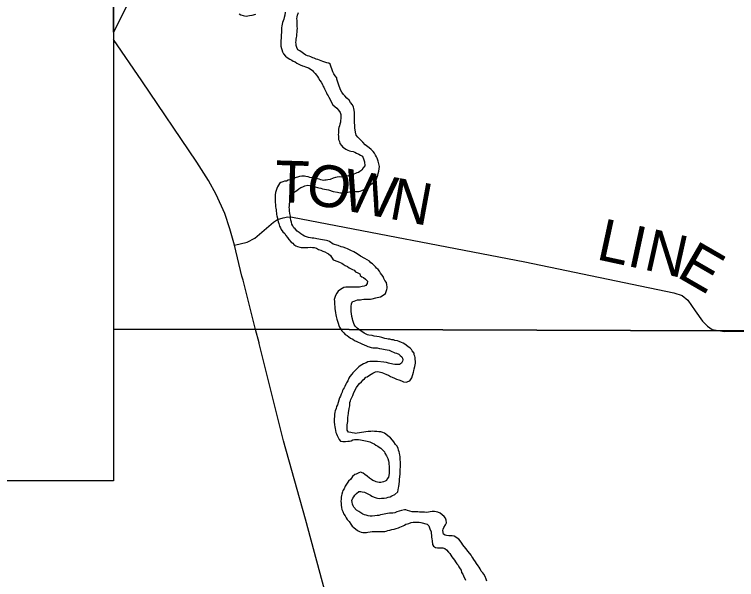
# Model space of a CAD drawing. Extents: x 0 to 34, y 0 to 22.
# Drawn here: x 5.775 to 6.756, y 14.874 to 15.642 of the extents above; entities that cross this region are included whole.
import ezdxf

# ---------------------------------------------------------------- set-up
doc = ezdxf.new("R2010")
doc.units = 0
for name, color, linetype in [('Default', 7, 'Continuous'), ('GM_X_Corporation', 7, 'Continuous'), ('GM_X_Minor_River', 7, 'Continuous'), ('GM_X_Township_Road', 7, 'Continuous'), ('GM_X_Township_Road_Text', 7, 'Continuous'), ('SH_Text', 7, 'Continuous')]:
    doc.layers.add(name, color=color, linetype=linetype)

msp = doc.modelspace()

# ---------------------------------------------------------------- linework, layer by layer
at = {"layer": 'Default'}
msp.add_lwpolyline([(5.90994, 15.72564), (6.64074, 17.07843), (5.90994, 15.61811)], close=True, dxfattribs=at)
at = {"layer": 'GM_X_Corporation'}
msp.add_lwpolyline([(5.90994, 15.72564), (5.90994, 15.21376), (6.10258, 15.21454), (6.73943, 15.21199), (6.94963, 15.21339), (8.01532, 15.22729), (7.992, 16.45338)], dxfattribs=at)
msp.add_lwpolyline([(3.69009, 15.2048), (3.5209, 15.20411), (2.73663, 15.2014), (2.74225, 14.8151), (2.77525, 14.15375), (2.77611, 14.09996), (8.03831, 14.09996), (8.03504, 14.24979), (8.03488, 14.25722), (8.02966, 14.49633), (8.02618, 14.65547), (8.01532, 15.22729), (6.94963, 15.21339), (6.73943, 15.21199), (6.10258, 15.21454), (5.90994, 15.21376), (5.90994, 15.00852), (3.69009, 15.00852)], close=True, dxfattribs=at)
at = {"layer": 'GM_X_Minor_River'}
for points in [[(6.08029, 15.64305), (6.08293, 15.6415), (6.08596, 15.6407), (6.08786, 15.6403), (6.08975, 15.6399), (6.09204, 15.64025), (6.09471, 15.6406), (6.09814, 15.64132), (6.10309, 15.6424)], [(6.14304, 15.64535), (6.14261, 15.64117), (6.14143, 15.63814), (6.14103, 15.63587), (6.14024, 15.6336), (6.13945, 15.63094), (6.13866, 15.62868), (6.13825, 15.62678), (6.13784, 15.62374), (6.13782, 15.62184), (6.13779, 15.61956), (6.13776, 15.61728), (6.13773, 15.61462), (6.13771, 15.61272), (6.13729, 15.61006), (6.13687, 15.60665), (6.13685, 15.60475), (6.13718, 15.60094), (6.13716, 15.59904), (6.13935, 15.59141), (6.14083, 15.58836), (6.14346, 15.58528), (6.14572, 15.58374), (6.14949, 15.58141), (6.15214, 15.57986), (6.15402, 15.5787), (6.15667, 15.57752), (6.15893, 15.57598), (6.16157, 15.57442), (6.16347, 15.57364), (6.16649, 15.57247), (6.16838, 15.57168), (6.17065, 15.5709), (6.17444, 15.56933), (6.1767, 15.56816), (6.1801, 15.56584)], [(6.20784, 15.5643), (6.20415, 15.57468), (6.20226, 15.57584), (6.19961, 15.57626), (6.19696, 15.57705), (6.19431, 15.57822), (6.19204, 15.57901), (6.18712, 15.58097), (6.18522, 15.58137), (6.1822, 15.58254), (6.18031, 15.58333), (6.17804, 15.58449), (6.17577, 15.58528), (6.17312, 15.58607), (6.17085, 15.58686), (6.16783, 15.58918), (6.16595, 15.59034), (6.16293, 15.59266), (6.16029, 15.59421), (6.15881, 15.59727), (6.15808, 15.59993), (6.15772, 15.60184), (6.15737, 15.60451), (6.15778, 15.6064), (6.1578, 15.6083), (6.15821, 15.61058), (6.15861, 15.61247), (6.15864, 15.61475), (6.15906, 15.61855), (6.15908, 15.62045), (6.1595, 15.62348), (6.15915, 15.62539), (6.15919, 15.62919), (6.15922, 15.63147), (6.15925, 15.63413), (6.15889, 15.63604), (6.15931, 15.63869), (6.15971, 15.64097), (6.1609, 15.64476)], [(6.1801, 15.56584), (6.18122, 15.56393), (6.18385, 15.56162), (6.18535, 15.5597), (6.18684, 15.55778), (6.18833, 15.55548), (6.1902, 15.55242), (6.19207, 15.55012), (6.19356, 15.54706), (6.19429, 15.54515), (6.19541, 15.54323), (6.19652, 15.54094), (6.19726, 15.53903), (6.19912, 15.53559), (6.20023, 15.53329), (6.20135, 15.53138), (6.20209, 15.52947), (6.2079, 15.51932)], [(6.20807, 15.40158), (6.21402, 15.40069), (6.21593, 15.4003), (6.21821, 15.3999), (6.22012, 15.39989), (6.22279, 15.40025), (6.22545, 15.40062), (6.22812, 15.4006), (6.23041, 15.40096), (6.23231, 15.40133), (6.23422, 15.40132), (6.23689, 15.40168), (6.24031, 15.40166), (6.24298, 15.40164), (6.24489, 15.40201), (6.24718, 15.40275), (6.25138, 15.40462), (6.2552, 15.40688), (6.26018, 15.41179), (6.26553, 15.41518), (6.26862, 15.42391), (6.26939, 15.42618), (6.27017, 15.42922), (6.27057, 15.43226), (6.27097, 15.4353), (6.2706, 15.4372), (6.27022, 15.43911), (6.26985, 15.44101), (6.2691, 15.44292), (6.26798, 15.44673), (6.26723, 15.44864), (6.26572, 15.45093), (6.2642, 15.4536), (6.26231, 15.4559), (6.25966, 15.45858), (6.257, 15.46088), (6.25511, 15.46203), (6.2517, 15.4651), (6.24867, 15.46854), (6.24601, 15.47084), (6.24374, 15.47314), (6.24184, 15.47543), (6.23919, 15.47811), (6.23845, 15.48192), (6.23772, 15.48801), (6.23701, 15.49829), (6.23702, 15.50019), (6.23703, 15.50209), (6.23704, 15.50399), (6.23705, 15.50627), (6.23707, 15.50894), (6.2367, 15.51198), (6.23633, 15.51427), (6.23596, 15.51617), (6.23445, 15.51922), (6.2318, 15.52228), (6.22992, 15.52572), (6.22689, 15.5284), (6.22385, 15.53147), (6.22234, 15.53338), (6.22007, 15.53643), (6.21818, 15.53949), (6.21705, 15.54254), (6.2163, 15.54483), (6.21518, 15.5475), (6.21443, 15.55017), (6.2133, 15.55398), (6.21293, 15.55588), (6.21104, 15.55855), (6.20915, 15.56161), (6.20784, 15.5643)], [(6.2079, 15.51932), (6.2131, 15.5148), (6.21537, 15.51212), (6.21764, 15.50869), (6.21839, 15.50602), (6.21875, 15.50297), (6.21874, 15.50107), (6.21834, 15.49765), (6.21795, 15.49575), (6.21718, 15.49309), (6.21678, 15.49082), (6.21601, 15.48854), (6.21562, 15.48626), (6.21522, 15.4836), (6.21521, 15.48094), (6.21482, 15.47904), (6.21519, 15.47675), (6.21518, 15.47485), (6.21554, 15.47219), (6.21667, 15.46952), (6.21742, 15.46685), (6.21931, 15.46418), (6.2212, 15.46188), (6.22348, 15.46034), (6.22538, 15.45881), (6.22804, 15.45765), (6.23032, 15.45687), (6.23222, 15.45648), (6.23527, 15.45608), (6.23755, 15.45492), (6.23982, 15.45339), (6.24286, 15.45223), (6.24514, 15.45107), (6.2478, 15.44953), (6.24968, 15.44457), (6.25081, 15.4419), (6.25116, 15.43619), (6.24886, 15.43355), (6.24732, 15.43052), (6.24427, 15.42863), (6.24235, 15.42751), (6.24045, 15.42676), (6.23854, 15.42601), (6.23625, 15.42527), (6.23396, 15.42414), (6.23129, 15.4234), (6.229, 15.42265), (6.22709, 15.42228), (6.22366, 15.42155), (6.22137, 15.42156), (6.21908, 15.4212), (6.21718, 15.42121), (6.21375, 15.42085), (6.21146, 15.42049), (6.20804, 15.41963)], [(6.20804, 15.41963), (6.20416, 15.41769), (6.20074, 15.41735), (6.19883, 15.41699), (6.19693, 15.41702), (6.19503, 15.41666), (6.19124, 15.41746), (6.18935, 15.41825), (6.18669, 15.41866), (6.18441, 15.41907), (6.18138, 15.41986), (6.17948, 15.41988), (6.17645, 15.42068), (6.17418, 15.42147), (6.17114, 15.42188), (6.16925, 15.42229), (6.16545, 15.42233), (6.1624, 15.42199), (6.15972, 15.42088), (6.15782, 15.42052), (6.15515, 15.41941), (6.15248, 15.41869), (6.1498, 15.41758), (6.14713, 15.41685), (6.14484, 15.41573), (6.14217, 15.41538), (6.13988, 15.41465), (6.13721, 15.41354), (6.1353, 15.41243), (6.13258, 15.4079), (6.13179, 15.40563), (6.12983, 15.40033), (6.12941, 15.39691), (6.12937, 15.39387), (6.12934, 15.39159), (6.12931, 15.38855), (6.12928, 15.38627), (6.12964, 15.38436), (6.12999, 15.38246), (6.12997, 15.38056), (6.13033, 15.37866), (6.13068, 15.37675), (6.13066, 15.37447), (6.13101, 15.37256), (6.13137, 15.37028), (6.13172, 15.36837), (6.13245, 15.36532), (6.1328, 15.36266), (6.13353, 15.36037), (6.13426, 15.35808), (6.135, 15.35617), (6.13536, 15.35427), (6.13647, 15.35197), (6.13759, 15.35006), (6.13982, 15.34661), (6.14246, 15.3443), (6.14395, 15.34162), (6.1462, 15.33893), (6.14806, 15.33625), (6.15106, 15.33279), (6.15332, 15.33125), (6.15482, 15.32933), (6.15746, 15.32778), (6.15973, 15.32661), (6.16276, 15.32581), (6.16466, 15.32541), (6.17112, 15.32534), (6.17378, 15.3253), (6.17721, 15.32602), (6.17987, 15.32561), (6.18252, 15.3252), (6.18555, 15.3244), (6.1882, 15.32285), (6.19122, 15.32168), (6.19425, 15.3205), (6.1969, 15.31933), (6.19992, 15.31777), (6.2018, 15.31661), (6.20444, 15.31468), (6.20819, 15.30886)], [(6.20816, 15.33001), (6.20315, 15.3337), (6.20088, 15.33448), (6.19898, 15.33489), (6.19367, 15.33571), (6.19102, 15.33612), (6.18875, 15.33691), (6.18609, 15.33732), (6.18419, 15.33772), (6.18192, 15.33813), (6.17964, 15.33816), (6.17736, 15.33856), (6.17471, 15.33898), (6.17205, 15.33977), (6.16941, 15.34094), (6.16676, 15.34211), (6.16412, 15.34404), (6.16186, 15.34597), (6.15922, 15.34752), (6.1566, 15.35059), (6.15472, 15.35214), (6.15323, 15.35482), (6.15212, 15.35711), (6.15139, 15.35978), (6.15066, 15.36245), (6.15031, 15.36511), (6.14997, 15.36816), (6.14925, 15.37159), (6.14891, 15.37501), (6.14895, 15.37805), (6.14859, 15.37996), (6.149, 15.38223), (6.14903, 15.38527), (6.14983, 15.38831), (6.15063, 15.39134), (6.1518, 15.39437), (6.15336, 15.39739), (6.15453, 15.39965), (6.15645, 15.40153), (6.15875, 15.40265), (6.16144, 15.40527), (6.16412, 15.40676), (6.16679, 15.40787), (6.16947, 15.40898), (6.17366, 15.41007), (6.17859, 15.40925), (6.18087, 15.40884), (6.18389, 15.40767), (6.18693, 15.40687), (6.18882, 15.40647), (6.19148, 15.40606), (6.19375, 15.40527), (6.1964, 15.40448), (6.19906, 15.40407), (6.20171, 15.40366), (6.20807, 15.40158)], [(6.30982, 15.14332), (6.31211, 15.14444), (6.31517, 15.14823), (6.3175, 15.15582), (6.31789, 15.15772), (6.31828, 15.16038), (6.31906, 15.1638), (6.31985, 15.16835), (6.31951, 15.17596), (6.31914, 15.17787), (6.31839, 15.17977), (6.31802, 15.18168), (6.31537, 15.18512), (6.31461, 15.18702), (6.31272, 15.18856), (6.30968, 15.19086), (6.30551, 15.19393), (6.30323, 15.19547), (6.30095, 15.19625), (6.29791, 15.19779), (6.29563, 15.19856), (6.29182, 15.19897), (6.28992, 15.19974), (6.28802, 15.20014), (6.28536, 15.20091), (6.28307, 15.20093), (6.28117, 15.20132), (6.2785, 15.20172), (6.27432, 15.20289), (6.27051, 15.20406), (6.26747, 15.20446), (6.26404, 15.20486), (6.261, 15.20564), (6.25682, 15.20643), (6.25491, 15.20683), (6.25035, 15.20914), (6.24845, 15.21029), (6.24618, 15.21183), (6.24276, 15.21451), (6.24086, 15.21567), (6.23821, 15.21873), (6.2367, 15.22064), (6.23557, 15.22369), (6.23482, 15.22636), (6.23445, 15.22826), (6.23371, 15.23169), (6.23297, 15.2355), (6.2326, 15.23816), (6.23262, 15.24159), (6.23263, 15.24349), (6.23264, 15.24539), (6.23304, 15.24881), (6.2342, 15.25222), (6.23649, 15.25259), (6.24107, 15.25408), (6.24335, 15.25444), (6.24526, 15.25443), (6.24716, 15.2548), (6.24983, 15.25516), (6.25174, 15.25515), (6.25478, 15.25513), (6.25897, 15.2551), (6.26126, 15.25547), (6.26622, 15.25695), (6.26813, 15.25732), (6.27232, 15.25843), (6.27729, 15.26144), (6.27921, 15.26295), (6.28114, 15.26826), (6.28153, 15.27016), (6.28154, 15.27206), (6.28117, 15.27473), (6.28043, 15.27778), (6.27854, 15.28045), (6.27703, 15.28312), (6.27589, 15.28579), (6.27439, 15.28847), (6.27249, 15.29038), (6.27098, 15.29343), (6.26947, 15.29535), (6.2672, 15.29726), (6.26568, 15.29917), (6.26341, 15.30147), (6.26151, 15.30301), (6.25923, 15.30454), (6.25734, 15.30684), (6.2543, 15.30876), (6.25127, 15.31068), (6.24519, 15.31377), (6.24063, 15.31684), (6.23607, 15.31953), (6.23228, 15.32146), (6.22962, 15.32262), (6.22772, 15.32377), (6.22543, 15.32455), (6.22163, 15.32571), (6.21897, 15.32649), (6.21479, 15.32804), (6.20816, 15.33001)], [(6.20819, 15.30886), (6.21429, 15.30637), (6.21771, 15.30482), (6.22, 15.30405), (6.22189, 15.30289), (6.22455, 15.30097), (6.22759, 15.29943), (6.22987, 15.2979), (6.23177, 15.29674), (6.23443, 15.29558), (6.23671, 15.29443), (6.2386, 15.29251), (6.24164, 15.29097), (6.2443, 15.28943), (6.24467, 15.28752), (6.24694, 15.28561), (6.24922, 15.28445), (6.25188, 15.28253), (6.25491, 15.27985), (6.25451, 15.27643), (6.2526, 15.27378), (6.25031, 15.27303), (6.24764, 15.27229), (6.24382, 15.27156), (6.24154, 15.27157), (6.23925, 15.27159), (6.23697, 15.2716), (6.23506, 15.27162), (6.23278, 15.27163), (6.23049, 15.27165), (6.22744, 15.27167), (6.22554, 15.2713), (6.22287, 15.27094), (6.22058, 15.26981), (6.2179, 15.26831), (6.21484, 15.26605), (6.21292, 15.2634), (6.21139, 15.26037), (6.20945, 15.25467), (6.20982, 15.25239), (6.21018, 15.2482), (6.21054, 15.24478), (6.21053, 15.24212), (6.2109, 15.23983), (6.21126, 15.23679), (6.21163, 15.23412), (6.21238, 15.23183), (6.21312, 15.22803), (6.21387, 15.22536), (6.215, 15.22269), (6.21574, 15.21964), (6.21687, 15.21697), (6.21838, 15.2143), (6.21989, 15.21201), (6.22254, 15.20933), (6.22444, 15.20741), (6.2271, 15.20587), (6.22937, 15.20396), (6.23165, 15.20242), (6.23469, 15.20088), (6.23735, 15.19896), (6.24039, 15.1978), (6.24229, 15.19664), (6.24419, 15.19587), (6.24723, 15.19433), (6.25027, 15.19316), (6.25331, 15.19162), (6.25521, 15.19085), (6.25711, 15.19046), (6.25977, 15.18968), (6.26206, 15.18928), (6.26472, 15.18888), (6.26777, 15.18886), (6.27119, 15.18808), (6.27424, 15.18768), (6.27881, 15.18689), (6.28147, 15.18649), (6.28413, 15.18571), (6.28604, 15.18494), (6.28793, 15.18416), (6.29022, 15.18339), (6.29211, 15.18223), (6.2944, 15.18184), (6.29744, 15.1803), (6.29933, 15.17876), (6.30123, 15.17685), (6.30236, 15.17494), (6.30273, 15.17266), (6.30234, 15.17075), (6.30118, 15.1681), (6.2985, 15.16622), (6.29508, 15.16662), (6.29203, 15.16664), (6.28937, 15.16704), (6.28747, 15.16743), (6.28518, 15.16783), (6.28328, 15.16822), (6.28062, 15.169)], [(6.28062, 15.169), (6.27719, 15.16978), (6.26844, 15.1706), (6.26539, 15.17062), (6.26272, 15.17064), (6.26082, 15.17065), (6.25777, 15.17029), (6.2551, 15.16993), (6.25281, 15.16881), (6.24937, 15.16731), (6.24708, 15.16618), (6.24479, 15.16468), (6.24287, 15.16317), (6.23981, 15.16015), (6.23675, 15.15712), (6.23483, 15.15523), (6.2333, 15.15334), (6.231, 15.15032), (6.22946, 15.14766), (6.22792, 15.14425), (6.22638, 15.1416), (6.22523, 15.13971), (6.22407, 15.13667), (6.22292, 15.13478), (6.22176, 15.13288), (6.22099, 15.13099), (6.22022, 15.12871), (6.21906, 15.12606), (6.2179, 15.1234), (6.21675, 15.12113), (6.21597, 15.11809), (6.21481, 15.11467), (6.21403, 15.11164), (6.21288, 15.10936), (6.2121, 15.10671), (6.21094, 15.10367), (6.21055, 15.10177), (6.21015, 15.09835), (6.20976, 15.09645), (6.20974, 15.09189), (6.20972, 15.08847), (6.21008, 15.08428), (6.21045, 15.08162), (6.21082, 15.07933), (6.21118, 15.07667), (6.21193, 15.074), (6.21268, 15.07209), (6.21343, 15.0698), (6.21494, 15.06713), (6.21645, 15.06446), (6.21796, 15.06217), (6.22139, 15.06177), (6.22482, 15.06174), (6.22825, 15.0621), (6.23054, 15.06246), (6.23244, 15.06283), (6.23474, 15.06396), (6.23702, 15.06432), (6.23969, 15.0643), (6.24236, 15.06429), (6.2454, 15.06388), (6.24997, 15.06309), (6.25225, 15.0627), (6.25415, 15.0623), (6.25606, 15.06191), (6.25796, 15.06114), (6.26138, 15.05959), (6.26366, 15.05844), (6.26632, 15.0569), (6.26897, 15.05536), (6.27087, 15.05421), (6.27277, 15.05267), (6.27466, 15.05114), (6.27769, 15.04769), (6.27845, 15.04579), (6.28072, 15.04235), (6.28222, 15.03891), (6.28334, 15.03548), (6.28371, 15.0332), (6.2837, 15.03054), (6.28407, 15.02863), (6.28405, 15.02521), (6.28404, 15.02293), (6.28403, 15.02103), (6.28402, 15.01837), (6.28323, 15.01343), (6.28169, 15.01116), (6.28054, 15.00888), (6.27863, 15.00775), (6.27672, 15.00701), (6.27291, 15.00627), (6.27062, 15.00629), (6.26834, 15.00668), (6.26643, 15.00708), (6.26454, 15.00785), (6.26225, 15.00901), (6.26036, 15.01016), (6.2577, 15.01208), (6.25429, 15.01476), (6.25125, 15.01707), (6.24897, 15.01898)], [(6.27394, 14.98458), (6.27737, 14.98494), (6.2808, 14.9853), (6.28309, 14.98605), (6.28538, 14.98679), (6.28805, 14.98791), (6.29187, 14.98979), (6.29608, 14.99356), (6.29647, 14.99622), (6.29687, 14.99888), (6.29726, 15.00078), (6.29765, 15.00382), (6.29844, 15.008), (6.29845, 15.01028), (6.29885, 15.01446), (6.29925, 15.0175), (6.29926, 15.02016), (6.29928, 15.02283), (6.29929, 15.02473), (6.29968, 15.02663), (6.29969, 15.02891), (6.2997, 15.03157), (6.29972, 15.03423), (6.29935, 15.0369), (6.29936, 15.03918), (6.29899, 15.04147), (6.29862, 15.04337), (6.29826, 15.04603), (6.29789, 15.04794), (6.29714, 15.05023), (6.29639, 15.05251), (6.2945, 15.05595), (6.29299, 15.05786), (6.29072, 15.0613), (6.28882, 15.06359), (6.28618, 15.06665), (6.28238, 15.06972), (6.27972, 15.07164), (6.27783, 15.07317), (6.27555, 15.07395), (6.27289, 15.07511), (6.27022, 15.07513), (6.26756, 15.07553), (6.26413, 15.07555), (6.26184, 15.07594), (6.25918, 15.07558), (6.25575, 15.07523), (6.2527, 15.07487), (6.24965, 15.07451), (6.24088, 15.07304), (6.23897, 15.07268), (6.23707, 15.07307), (6.23402, 15.07347), (6.23212, 15.07386), (6.22908, 15.07464), (6.22719, 15.07732), (6.2272, 15.07998), (6.22721, 15.08226), (6.22722, 15.08455), (6.22762, 15.08682), (6.22801, 15.0891), (6.22802, 15.09138), (6.22804, 15.09405), (6.22843, 15.09747), (6.22882, 15.09937), (6.22883, 15.10127), (6.22961, 15.10355), (6.23001, 15.10659), (6.23079, 15.11038), (6.23081, 15.11457), (6.23158, 15.11684), (6.23236, 15.11874), (6.23313, 15.12064), (6.23467, 15.12443), (6.23622, 15.12822), (6.23968, 15.13505), (6.24198, 15.13845), (6.2439, 15.14072), (6.24658, 15.14299), (6.24888, 15.14563), (6.25079, 15.14714), (6.25232, 15.14903), (6.25423, 15.14978), (6.25767, 15.15204), (6.26188, 15.15467), (6.2657, 15.15655), (6.26875, 15.15691), (6.27065, 15.15652), (6.27407, 15.15535), (6.27673, 15.15457), (6.28053, 15.15264), (6.28319, 15.15187), (6.28623, 15.15033), (6.28813, 15.14917), (6.29155, 15.14763), (6.29421, 15.14647), (6.29725, 15.14569), (6.30106, 15.14414), (6.30372, 15.14298), (6.30791, 15.14257), (6.30982, 15.14332)], [(6.24897, 15.01898), (6.24517, 15.02015), (6.24288, 15.0194), (6.23944, 15.01752), (6.23754, 15.01678), (6.23447, 15.01414), (6.23217, 15.01073), (6.22911, 15.00771), (6.22642, 15.00392), (6.2245, 15.00089), (6.22296, 14.99748), (6.22142, 14.99521), (6.22103, 14.99331), (6.21987, 14.99027), (6.21948, 14.98837), (6.21909, 14.98609), (6.21907, 14.98343), (6.21868, 14.98077), (6.21904, 14.97735), (6.21903, 14.97544), (6.2194, 14.97202), (6.22014, 14.96935), (6.22127, 14.96668), (6.22278, 14.96325), (6.22467, 14.96058), (6.2258, 14.95829), (6.22731, 14.95599), (6.22996, 14.95293), (6.23223, 14.9495), (6.23412, 14.94682), (6.23601, 14.94491), (6.24132, 14.94069), (6.24399, 14.93953), (6.24627, 14.93875), (6.24855, 14.93836), (6.25046, 14.93834), (6.2535, 14.93832), (6.25541, 14.93869), (6.25846, 14.93905), (6.26113, 14.93941), (6.26494, 14.93939), (6.26913, 14.93936), (6.27332, 14.93933), (6.27599, 14.93969), (6.27827, 14.93968), (6.28018, 14.94005), (6.28247, 14.94079), (6.28514, 14.94153), (6.28781, 14.94228), (6.29124, 14.94263), (6.29353, 14.94338), (6.29696, 14.9445), (6.29887, 14.94524), (6.30116, 14.94637), (6.30307, 14.94712), (6.30498, 14.94825), (6.30689, 14.94937), (6.30918, 14.95012), (6.31109, 14.95048), (6.31414, 14.95161), (6.31681, 14.95197), (6.31986, 14.95233), (6.32253, 14.95231), (6.32481, 14.95229), (6.32748, 14.9519), (6.33584, 14.94956), (6.33812, 14.94726), (6.33962, 14.94307), (6.34112, 14.93887), (6.34149, 14.93659), (6.34186, 14.93469), (6.34185, 14.93202), (6.34221, 14.92936), (6.34258, 14.92669), (6.34332, 14.92175), (6.34445, 14.91945), (6.34711, 14.91791), (6.34977, 14.91752), (6.35282, 14.91712), (6.35472, 14.91748), (6.35701, 14.91747), (6.36005, 14.91631), (6.36232, 14.91439), (6.36498, 14.91133), (6.36687, 14.90942), (6.36952, 14.90521), (6.37103, 14.90292), (6.37292, 14.90063), (6.37443, 14.89834), (6.37632, 14.89566), (6.37784, 14.89375), (6.37897, 14.89146), (6.38048, 14.88879), (6.38199, 14.88687), (6.38273, 14.88383), (6.38425, 14.88154), (6.38538, 14.87925), (6.38802, 14.87352)], [(6.41282, 14.88134), (6.4113, 14.88325), (6.40941, 14.88555), (6.4079, 14.8886), (6.40639, 14.89089), (6.40526, 14.8928), (6.40299, 14.89624), (6.40148, 14.89815), (6.39921, 14.90159), (6.3977, 14.9035), (6.39656, 14.90541), (6.39543, 14.90732), (6.39392, 14.90961), (6.39127, 14.91267), (6.38862, 14.91612), (6.38635, 14.91917), (6.38446, 14.92147), (6.38295, 14.92376), (6.38068, 14.92682), (6.37878, 14.92911), (6.3765, 14.93065), (6.37461, 14.9318), (6.37271, 14.93296), (6.37005, 14.93373), (6.36738, 14.93375), (6.36509, 14.93377), (6.36205, 14.93417), (6.36014, 14.93456), (6.35787, 14.93572), (6.35713, 14.94067), (6.35752, 14.94257), (6.35829, 14.94484), (6.36098, 14.94863), (6.36214, 14.95128), (6.36178, 14.95471), (6.36065, 14.95776), (6.35875, 14.96005), (6.3561, 14.96235), (6.35344, 14.96427), (6.3504, 14.96581), (6.34812, 14.96621), (6.34584, 14.96661), (6.34279, 14.96663), (6.34012, 14.96627), (6.33745, 14.9659), (6.3344, 14.96554), (6.33212, 14.96556), (6.32945, 14.96596), (6.32564, 14.96598), (6.32298, 14.96638), (6.31917, 14.96602), (6.31536, 14.96643), (6.31232, 14.96721), (6.30928, 14.96799), (6.307, 14.96877), (6.30509, 14.96878), (6.30089, 14.96805), (6.29479, 14.96619), (6.29174, 14.96469), (6.28907, 14.96433), (6.28678, 14.96434), (6.28488, 14.96435), (6.28183, 14.96399), (6.27992, 14.96363), (6.27725, 14.96288), (6.27534, 14.96252), (6.27268, 14.96215), (6.27039, 14.96141), (6.2681, 14.96104), (6.26467, 14.96069), (6.26124, 14.96033), (6.25857, 14.96035), (6.25553, 14.96075), (6.25286, 14.96153), (6.25058, 14.9623), (6.24868, 14.96308), (6.24564, 14.965), (6.24298, 14.96654), (6.23995, 14.96846), (6.23616, 14.97267), (6.23541, 14.97458), (6.23428, 14.97686), (6.23391, 14.97953), (6.23354, 14.98144), (6.23508, 14.98485), (6.23623, 14.98674), (6.23777, 14.98901), (6.23969, 14.99128), (6.24313, 14.99392), (6.2458, 14.9939), (6.2477, 14.99351), (6.25074, 14.99273), (6.25416, 14.99118), (6.25606, 14.99003), (6.25872, 14.98887), (6.26062, 14.98772), (6.26366, 14.98617), (6.2667, 14.98539), (6.2686, 14.98462), (6.27089, 14.98422), (6.27394, 14.98458)], [(6.41696, 14.87219), (6.41621, 14.87485), (6.4147, 14.87829), (6.41282, 14.88134)]]:
    msp.add_lwpolyline(points, dxfattribs=at)
at = {"layer": 'GM_X_Township_Road'}
for points in [[(6.10742, 15.19589), (6.10279, 15.21399), (6.08569, 15.28084), (6.08422, 15.28657), (6.07419, 15.32877), (6.06785, 15.35082), (6.06112, 15.37174), (6.04911, 15.39724), (6.03859, 15.41627), (6.02279, 15.44141), (5.94825, 15.55189), (5.90994, 15.60791)], [(6.07419, 15.32877), (6.09151, 15.33267), (6.10177, 15.33795), (6.12689, 15.35987), (6.1326, 15.36343), (6.14019, 15.3659), (6.14666, 15.36704), (6.15309, 15.3666), (6.46832, 15.30614), (6.67095, 15.26388), (6.68233, 15.26008), (6.68993, 15.25362), (6.70017, 15.23956), (6.71005, 15.22512), (6.71506, 15.2201)], [(6.71506, 15.2201), (6.7165, 15.21866), (6.72295, 15.2141), (6.73964, 15.21144), (6.94984, 15.21284)], [(6.37389, 14.29712), (6.35214, 14.34315), (6.28494, 14.48558), (6.2743, 14.5114), (6.26481, 14.53913), (6.25416, 14.60293), (6.24086, 14.69484), (6.23857, 14.70585), (6.22756, 14.74459), (6.17059, 14.95616), (6.14077, 15.06263), (6.10766, 15.19493), (6.10742, 15.19589)]]:
    msp.add_lwpolyline(points, dxfattribs=at)
at = {"layer": 'SH_Text'}
msp.add_lwpolyline([(3.69009, 15.72564), (5.90994, 15.72564), (5.90994, 15.00852), (3.69009, 15.00852)], close=True, dxfattribs=at)

# ---------------------------------------------------------------- texts
at = {"layer": 'GM_X_Township_Road_Text'}
for s, rotation, p in [('T', 358.27273, (6.12842, 15.38704)), ('O', 349.51595, (6.16863, 15.386)), ('W', 349.47144, (6.21778, 15.37691)), ('N', 349.47164, (6.2825, 15.36488)), ('L', 347.78731, (6.56425, 15.30973)), ('I', 347.77768, (6.60579, 15.30074)), ('N', 347.43405, (6.6285, 15.29582)), ('E', 329.98667, (6.67306, 15.2866))]:
    msp.add_text(s, height=0.05682, rotation=rotation, dxfattribs=at).set_placement(p)

doc.saveas('drawing.dxf')
